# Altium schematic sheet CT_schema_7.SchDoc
size 278 x 170 mm
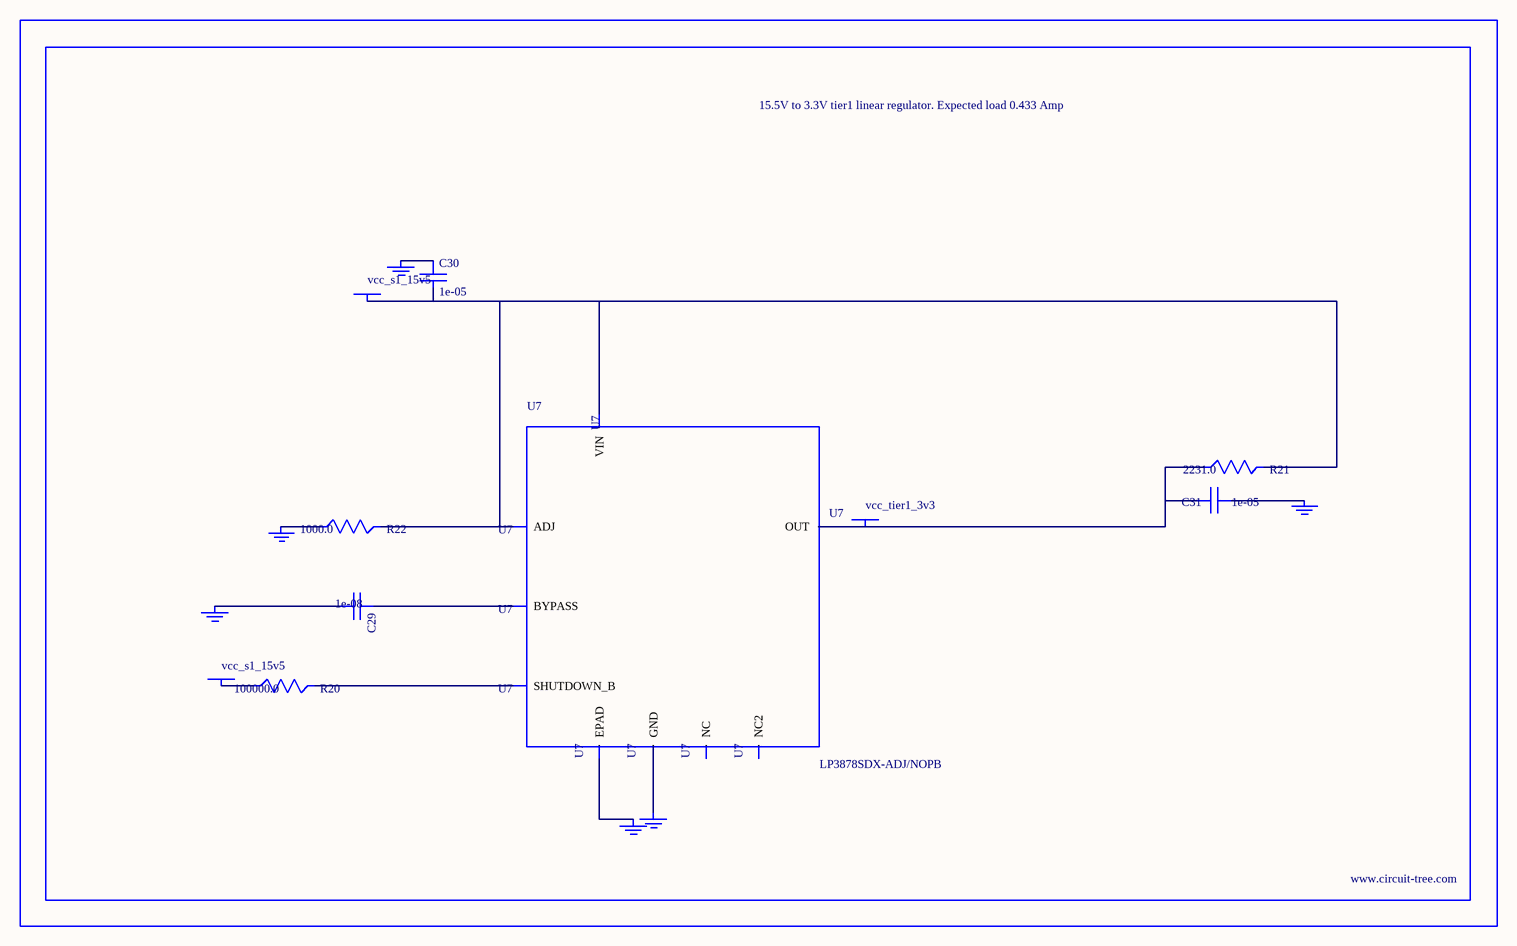
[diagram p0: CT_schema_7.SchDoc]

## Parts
BORDER6  (no value)
C29  1e-08  [C0402]
C30  1e-05  [C1210]
C31  1e-05  [C1210]
GND_INSTANCE_6_0  (no value)
GND_INSTANCE_6_1  (no value)
GND_INSTANCE_6_2  (no value)
GND_INSTANCE_6_3  (no value)
GND_INSTANCE_6_4  (no value)
GND_INSTANCE_6_5  (no value)
POWER_INSTANCE_6_0  vcc_s1_15v5
POWER_INSTANCE_6_1  vcc_s1_15v5
POWER_INSTANCE_6_2  vcc_tier1_3v3
R20  100000.0  [R0603]
R21  2231.0  [R0603]
R22  1000.0  [R0603]
U7  LP3878SDX-ADJ/NOPB  [WSON-8]

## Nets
NetC29_1: C29.1 U7.1(BYPASS)
NetC29_2: C29.2 GND_INSTANCE_6_0.0(GND)
NetC30_1: C30.1 GND_INSTANCE_6_1.0(GND)
NetC30_2: C30.2 POWER_INSTANCE_6_0.0(PWR) R21.2 R22.2 U7.4(VIN) U7.6(ADJ)
NetC31_1: C31.1 GND_INSTANCE_6_2.0(GND)
NetC31_2: C31.2 POWER_INSTANCE_6_2.0(PWR) R21.1 U7.5(OUT)
NetGND_INSTANCE_6_3_0: GND_INSTANCE_6_3.0(GND) R22.1
NetGND_INSTANCE_6_4_0: GND_INSTANCE_6_4.0(GND) U7.PAD(EPAD)
NetGND_INSTANCE_6_5_0: GND_INSTANCE_6_5.0(GND) U7.3(GND)
NetPOWER_INSTANCE_6_1_0: POWER_INSTANCE_6_1.0(PWR) R20.1
NetR20_2: R20.2 U7.8(SHUTDOWN_B)

Not connected (* = marked no-connect by the designer): U7 2(NC) 7(NC2)

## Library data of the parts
BORDER6 = BORDER_PAGE6
C29 = C0402C103K3RAC
C30 = C1210C106K5PACTU
C31 = GRM32DR61E106MA12L
GND_INSTANCE_6_0-GND_INSTANCE_6_5 = GND
POWER_INSTANCE_6_0-POWER_INSTANCE_6_2 = PWR
R20 = RC0603JR-07100KL
R21 = R21
R22 = RC0603JR-071KL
